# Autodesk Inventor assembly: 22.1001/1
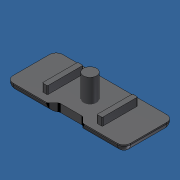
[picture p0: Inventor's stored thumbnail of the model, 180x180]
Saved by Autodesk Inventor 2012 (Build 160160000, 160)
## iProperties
Created: 2013-03
Part Number: 22.1001/1
Document SubType Name: Assembly
Designer: Admin
Description: END CAP 19X45 GRAY
Mass: 2.8313 g
Surface Area: 23.1313 cm^2
Volume: 2.67104 cm^3
Density: 1.06 g/cm^3
Author: Admin
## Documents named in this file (3)
- C:\Andys Backup Data\ANDY'S INVENTOR\INVENTOR LIBRARIES\PARTS LIBRARY\END CAPS\22.1001_1 END CAP 19X45.iam
- C:\Andys Backup Data\ANDY'S INVENTOR\INVENTOR LIBRARIES\PARTS LIBRARY\END CAPS\SUBCOMPONENTS\END CAP DOWEL GRAY.ipt
- C:\Andys Backup Data\ANDY'S INVENTOR\INVENTOR LIBRARIES\PARTS LIBRARY\END CAPS\SUBCOMPONENTS\22.1001_1 END CAP 19X45 GRAY.ipt
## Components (2 placed, 2 different names)
1. 22.1001_1 END CAP 19X45 GRAY:1 — Insert:1
2. END CAP DOWEL GRAY:1 — Insert:1
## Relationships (1: Insert 1)
- Insert:1: 22.1001_1 END CAP 19X45 GRAY:1 ↔ END CAP DOWEL GRAY:1
